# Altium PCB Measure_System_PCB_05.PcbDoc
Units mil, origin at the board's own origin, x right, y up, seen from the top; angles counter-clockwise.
Board outline 5905.51 x 3943.07 mil, 2 copper layers (Top Layer, Bottom Layer); 42 components, 30 nets, 113 pads, 0 vias.
Unrouted connection lines stored in the file: 1.
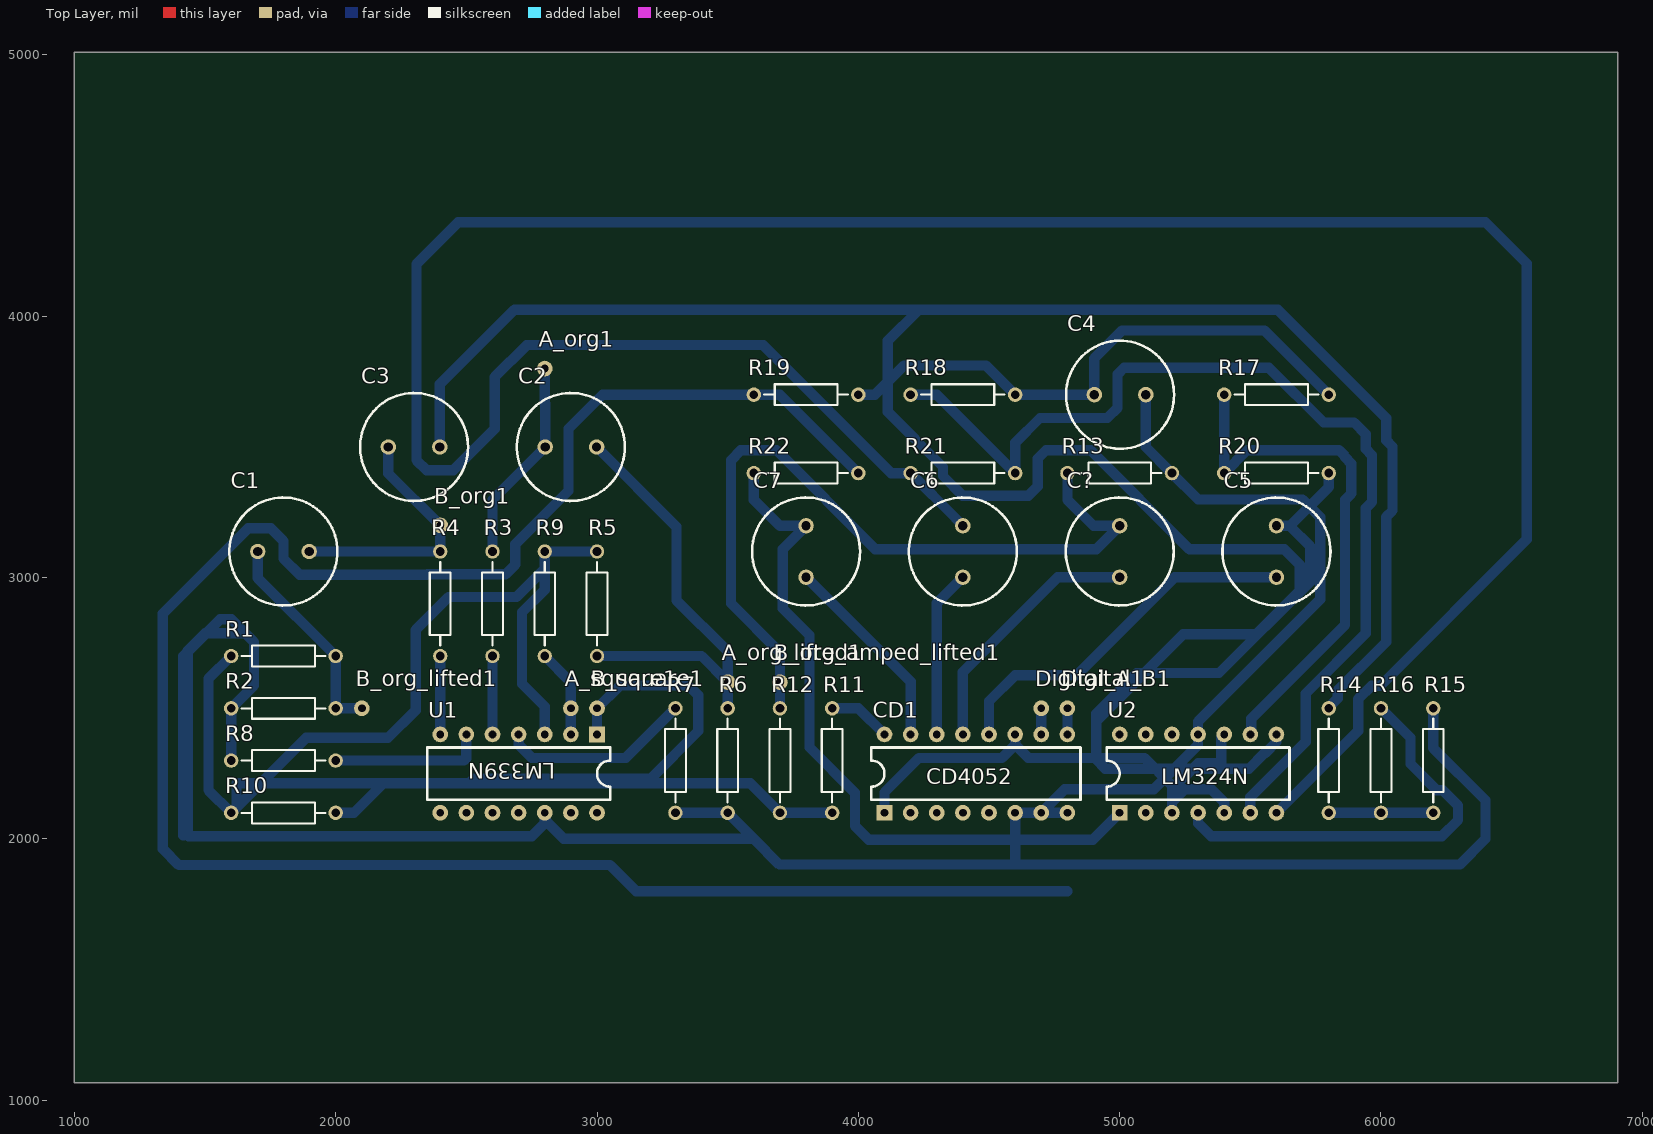
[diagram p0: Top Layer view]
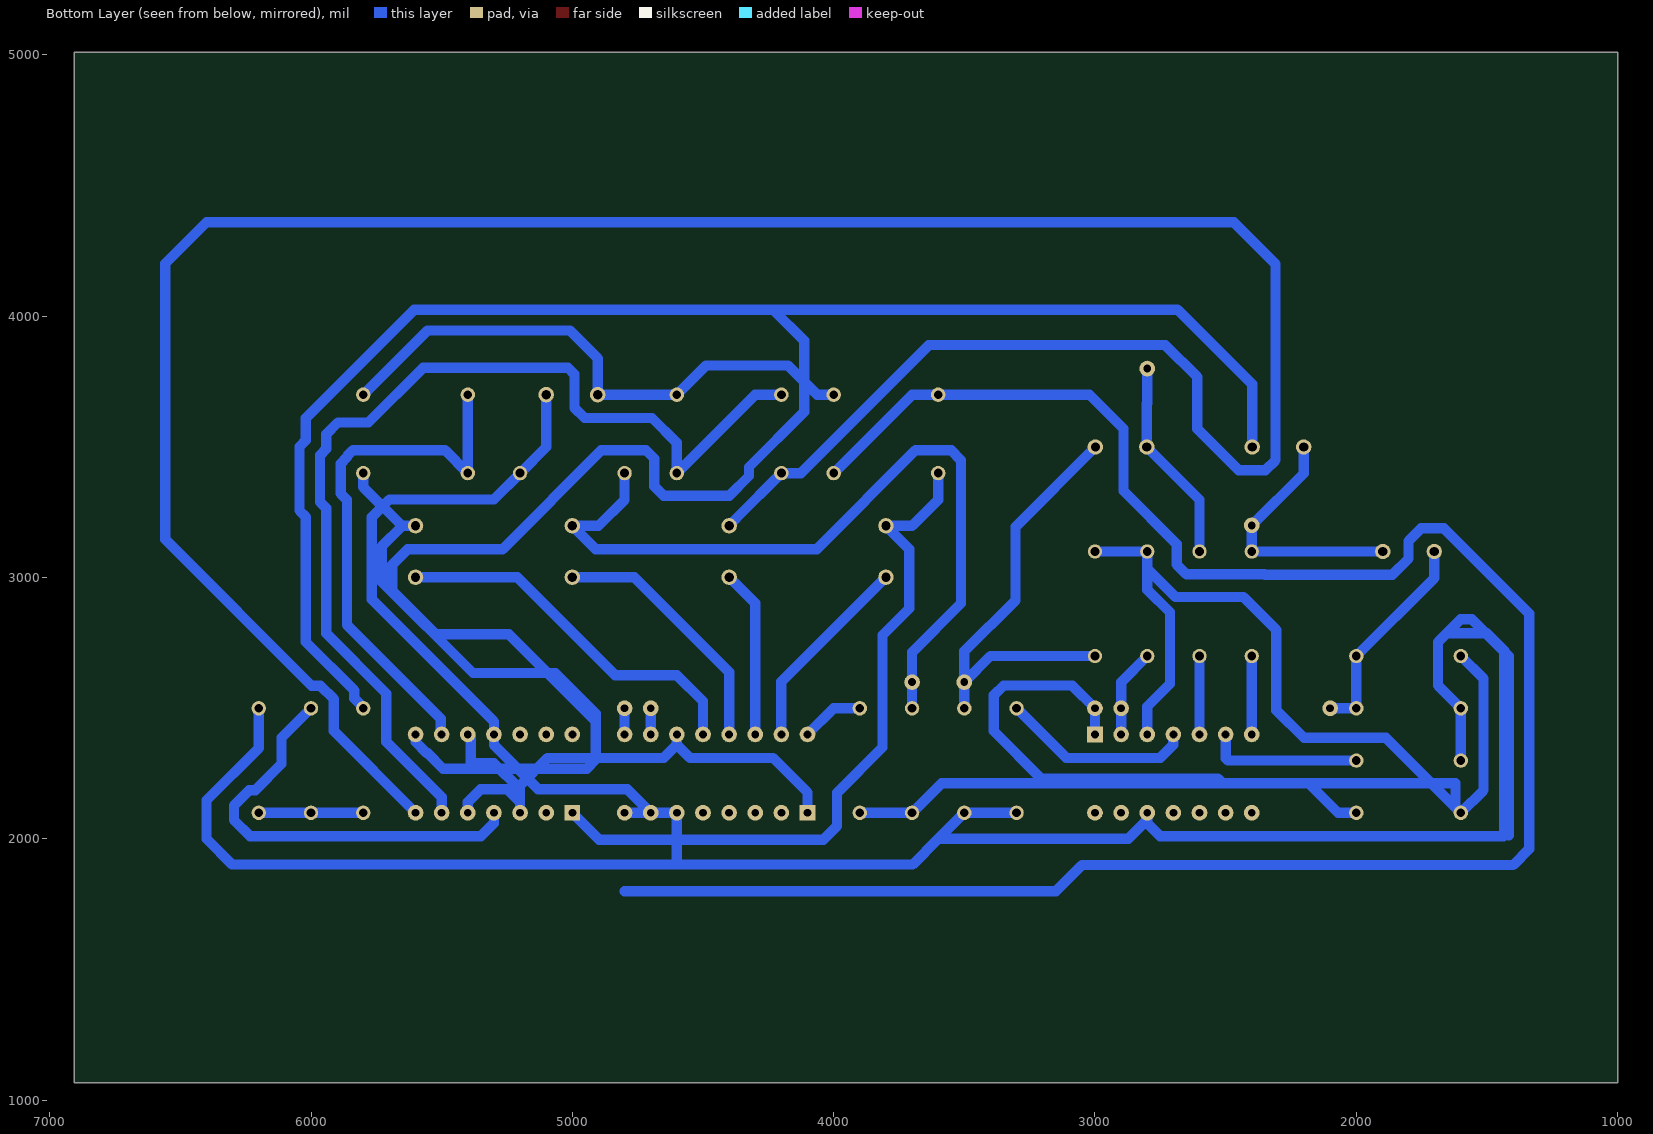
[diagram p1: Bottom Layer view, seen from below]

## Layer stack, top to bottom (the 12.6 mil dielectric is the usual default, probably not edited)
Top Solder: solder mask 0.4, Solder Resist, Dk 3.5
Top Layer: signal copper 1.4
Dielectric 1: dielectric 12.6, FR-4, Dk 4.8
Bottom Layer: signal copper 1.4
Bottom Solder: solder mask 0.4, Solder Resist, Dk 3.5

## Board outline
1000,1066.93 1000,5010 6905.51,5010 6905.51,1066.93

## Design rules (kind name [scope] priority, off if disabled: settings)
Clearance [All] p1: gap=39.37 ignorepadtopadclearanceinfootprint=FALSE
PolygonConnect [All] p1: connectstyle=Relief reliefconductorwidth=10 reliefentries=4 polygonreliefangle="90 Angle" airgapwidth=10
RoutingLayers [All] p1: top layer_v5=FALSE bottom layer_v5=TRUE
RoutingVias [All] p1: holewidth=28 width=50 viastyle="Through Hole" minholewidth=28 minwidth=50 maxholewidth=28 maxwidth=50
SolderMaskExpansion [All] p1: expansion=4 istentingtop=FALSE
Width [All] p1: maxlimit=393.7 minlimit=19.68 preferedwidth=39.37 minimp=50.000000 maximp=50.000000 favimp=50.000000
29 further rules are at their usual default settings.

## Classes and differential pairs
component class Part_Square: C1 C2 R1 R2 R3 R4 R5 R6 R7 R8 R9 R10 U1
component class Part_PGA: C3 C4 C5 C6 C7 C? CD1 R11 R12 R13 R14 R15 R16 R17 R18 R19 R20 R21 R22 U2
component class Measure_System_Main: A_org1 A_org_lifted1 A_square1 B_org1 B_org_amped_lifted1 B_org_lifted1 B_square1 Digital_A1 Digital_B1

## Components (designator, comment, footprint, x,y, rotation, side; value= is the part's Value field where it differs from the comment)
A_org1 "Hole" Hole 2800,3800 r90 top
A_org_lifted1 "Hole" Hole 3500,2600 r90 top
A_square1 "Hole" Hole 2900,2500 r90 top
B_org1 "Hole" Hole 2400,3200 r90 top
B_org_amped_lifted1 "Hole" Hole 3700,2600 r90 top
B_org_lifted1 "Hole" Hole 2100,2500 r0 top
B_square1 "Hole" Hole 3000,2500 r90 top
C1 "Cap Pol1" RB5-10.5 1800,3100 r180 top value=10u
C2 "Cap Pol1" RB5-10.5 2900,3500 r0 top value=10u
C3 "Cap Pol1" RB5-10.5 2300,3500 r0 top value=10u
C4 "Cap Pol1" RB5-10.5 5001.57,3700 r180 top value=10u
C5 "Cap Pol1" RB5-10.5 5600,3100 r270 top value=10u
C6 "Cap Pol1" RB5-10.5 4400,3100 r270 top value=10u
C7 "Cap Pol1" RB5-10.5 3800,3100 r270 top value=10u
C? "Cap Pol1" RB5-10.5 5000,3100 r90 top value=10u
CD1 "CD4052" CD4052 4100,2100 r90 top
Digital_A1 "Hole" Hole 4700,2500 r90 top
Digital_B1 "Hole" Hole 4800,2500 r90 top
R1 "Res2" AXIAL-0.4 1800,2700 r180 top value=100k
R2 "Res2" AXIAL-0.4 1800,2500 r0 top value=100k
R3 "Res2" AXIAL-0.4 2600,2900 r90 top value=1k
R4 "Res2" AXIAL-0.4 2400,2900 r90 top value=1k
R5 "Res2" AXIAL-0.4 3000,2900 r90 top value=100k
R6 "Res2" AXIAL-0.4 3500,2300 r90 top value=100k
R7 "Res2" AXIAL-0.4 3300,2300 r90 top value=10k
R8 "Res2" AXIAL-0.4 1800,2300 r180 top value=10k
R9 "Res2" AXIAL-0.4 2800,2900 r270 top value=10k
R10 "Res2" AXIAL-0.4 1800,2100 r180 top value=10k
R11 "Res2" AXIAL-0.4 3900,2300 r270 top value=200
R12 "Res2" AXIAL-0.4 3700,2300 r270 top value=100k
R13 "Res2" AXIAL-0.4 5000,3400 r180 top value=100k
R14 "Res2" AXIAL-0.4 5800,2300 r90 top value=100k
R15 "Res2" AXIAL-0.4 6200,2300 r270 top value=100k
R16 "Res2" AXIAL-0.4 6000,2300 r270 top value=100k
R17 "Res2" AXIAL-0.4 5600,3700 r180 top value=50k
R18 "Res2" AXIAL-0.4 4400,3700 r180 top value=24k
R19 "Res2" AXIAL-0.4 3800,3700 r180 top value=12k
R20 "Res2" AXIAL-0.4 5600,3400 r0 top value=100k
R21 "Res2" AXIAL-0.4 4400,3400 r180 top value=100k
R22 "Res2" AXIAL-0.4 3800,3400 r180 top value=100k
U1 "LM339N" LM339N 3000,2400 r270 top
U2 "LM324N" LM324N 5000,2100 r90 top

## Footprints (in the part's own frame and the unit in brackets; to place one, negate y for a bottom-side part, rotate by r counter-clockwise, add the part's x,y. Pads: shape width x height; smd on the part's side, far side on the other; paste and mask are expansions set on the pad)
AXIAL-0.4 [mm] "Axial Device, Thru-Hole; 2 Leads; 0.4 in Pin Spacing"
  round 1.4 hole 0.85: 1(-5.08,0) 2(5.08,0)
  silkscreen extent -4.06,-1.02 4.06,1.02
CD4052 [mil]
  rect 60x60 hole 30: 1(0,0)
  round 60 hole 30 mask+4: 2(0,-100) 3(0,-200) 4(0,-300) 5(0,-400) 6(0,-500) 7(0,-600) 8(0,-700) 9(300,-700) 10(300,-600) 11(300,-500) 12(300,-400) 13(300,-300) 14(300,-200) 15(300,-100) 16(300,0)
  silkscreen extent 50,-750 250,50
Hole [mil]
  round 60 hole 30 mask+4: 1(0,0)
LM324N [mil]
  rect 60x60 hole 30: 1(0,0)
  round 60 hole 30 mask+4: 2(0,-100) 3(0,-200) 4(0,-300) 5(0,-400) 6(0,-500) 7(0,-600) 8(300,-600) 9(300,-500) 10(300,-400) 11(300,-300) 12(300,-200) 13(300,-100) 14(300,0)
  silkscreen extent 50,-650 250,50
LM339N [mil]
  rect 60x60 hole 30: 1(0,0)
  round 60 hole 30 mask+4: 2(0,-100) 3(0,-200) 4(0,-300) 5(0,-400) 6(0,-500) 7(0,-600) 8(300,-600) 9(300,-500) 10(300,-400) 11(300,-300) 12(300,-200) 13(300,-100) 14(300,0)
  silkscreen extent 50,-650 250,50
RB5-10.5 [mm] "Capacitor (Radial); 2 Leads"
  round 1.5 hole 0.9: 1(-2.5,0) 2(2.5,0)
  silkscreen extent -5.25,-5.25 5.25,5.25

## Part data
C1 C2 C3 C4 C5 C6 C7 C?: "Polarized Capacitor (Radial)"
R1 R2 R3 R4 R5 R6 R7 R8 R9 R10 R11 R12 R13 R14 R15 R16 R17 R18 R19 R20 R21 R22: "Resistor"

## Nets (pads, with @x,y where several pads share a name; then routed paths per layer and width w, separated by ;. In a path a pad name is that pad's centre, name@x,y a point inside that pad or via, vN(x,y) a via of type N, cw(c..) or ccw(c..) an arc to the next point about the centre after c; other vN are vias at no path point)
+5: R1.2 R5.2 R9.1 R10.2 R11.2 R12.2 U1.3 | length 5830.9
  Bottom Layer w39.37: R1.2 1513,2613 1513,2187 R10.2 1620,2120 ; U1.3 2800,2507 2713,2594 2713,2867 2800,2954 2800,3034.64 ; R5.2 R9.1 2800,3034.64 ; R11.2 R12.2 3587,2213 1713,2213 ; 1620,2120 1713,2213 ; 1620,2120 1620,2213 1713,2213 ; 1713,2213 1887,2387 2200,2387 2306,2493 2306,2800 2431.5,2925.5 2690.86,2925.5 2800,3034.64
+12: R16.1 U2.4 | length 1644.4
  Bottom Layer w39.37: U2.4 5300,2060 5350,2010 6232.49,2010 6294.94,2072.45 6294.94,2127.55 6235.88,2186.61 6213.39,2186.61 6113,2287 6113,2387 R16.1
B_org: B_org1.1 C1.1 C3.1 R4.2 | length 983.8
  Bottom Layer w39.37: C1.1 R4.2 B_org1.1 2201.57,3398.43 C3.1
B_org_amp_1: C3.2 CD1.1 CD1.11 R14.2 U2.3 U2.5 U2.10 | length 11174.7
  Bottom Layer w39.37: C3.2 2398.43,3739.48 2683.94,4025 4232,4025 ; CD1.1 4100,2178 4232,2310 4550,2310 4600,2360 ; CD1.11 4600,2360 ; U2.3 5200,2140 ; U2.5 5400,2140 5350,2190 5250,2190 5200,2140 ; U2.10 5389,2389 5389,2290 5300,2290 5200,2190 ; R14.2 5800,2504.26 5834.65,2538.91 5834.65,2568.49 6020,2753.85 6020,3232.43 6044.09,3256.52 6044.09,3501.11 6020,3525.2 6020,3610 5605,4025 4232,4025 ; 4232,4025 4113,3906 4113,3634.4 4324,3423.4 4324,3389 4400,3313 4650,3313 4687,3350 4687,3456 4718,3487 4889,3487 5267,3109 5630,3109 5689,3050 5689,2950 5522.7,2783.7 5243.7,2783.7 4910,2450 4910,2317 4903,2310 ; 4600,2360 4650,2310 4903,2310 ; 4903,2310 5095,2310 5200,2205 5200,2190 ; 5200,2140 5200,2190
B_org_amp_2.5: C5.2 CD1.12 | length 1423.6
  Bottom Layer w39.37: CD1.12 4500,2527 4600,2627 4836.33,2627 5210.9,3001.57 C5.2
B_org_amp_5: C6.2 CD1.14 | length 643
  Bottom Layer w39.37: CD1.14 4300,2901.57 C6.2
B_org_amp_10: C7.2 CD1.15 | length 767.3
  Bottom Layer w39.37: C7.2 4200,2601.57 CD1.15
B_org_amped: C?.1 CD1.13 | length 989
  Bottom Layer w39.37: CD1.13 4400,2638.64 4762.93,3001.57 C?.1
Digital_A: CD1.10 Digital_A1.1 | length 100
  Bottom Layer w39.37: CD1.10 Digital_A1.1
Digital_B: CD1.9 Digital_B1.1 | length 100
  Bottom Layer w39.37: CD1.9 Digital_B1.1
GND: C4.1 CD1.6 CD1.7 CD1.8 R2.1 R6.1 R7.1 R8.2 R13.1 R15.1 U1.12 U2.11 | length 11731.4
  Bottom Layer w39.37: 1417,2013 1417,2700 1434,2717 ; R8.2 R2.1 1687,2587 1687,2754 1600,2841 1558,2841 1504,2787 ; 1650,2787 1504,2787 ; R7.1 R6.1 3599,2001 ; CD1.8 CD1.7 ; C4.1 5100,3500 R13.1 5301,3299 5700,3299 5768,3231 5768,2917.64 5300,2449.64 U2.11 5300,2360 5130,2190 4790,2190 CD1.7 ; R15.1 6200,2347.87 6400,2147.87 6400,2000 6302,1902 4600,1902 ; 1434,2717 1434,2721 1500,2787 1504,2787 ; 1434,2717 1434,2013 1437,2010 2750,2010 2800,2060 U1.12 2803.95,2096.05 2803.95,2070.11 2873.06,2001 3599,2001 ; 1434,2717 1504,2787 ; 3599,2001 3698,1902 4600,1902 ; 4600,1902 CD1.6 CD1.7
NetA_org1_1: A_org1.1 C2.1 R3.2 | length 784.1
  Bottom Layer w39.37: R3.2 2600,3298.43 C2.1 2801.57,3665.75 2800,3667.33 A_org1.1
NetA_org_lifted1_1: A_org_lifted1.1 C2.2 R5.1 R6.2 | length 1749.2
  Bottom Layer w39.37: C2.2 3303.97,3194.45 3303.97,2913.83 3500,2717.8 A_org_lifted1.1 ; R5.1 3400,2700 A_org_lifted1.1 ; R6.2 3500,2549 A_org_lifted1.1
NetA_square1_1: A_square1.1 R9.2 U1.2 | length 341.4
  Bottom Layer w39.37: R9.2 2900,2600 A_square1.1 U1.2
NetB_org_amped_lifted1_1: B_org_amped_lifted1.1 C?.2 R12.1 R13.2 | length 3066.4
  Bottom Layer w39.37: R12.1 B_org_amped_lifted1.1 3700,2714 3513,2901 3513,3450 3550,3487 3687,3487 4065,3109 4910.57,3109 C?.2 4900,3198.43 4800,3298.43 R13.2
NetB_org_lifted1_1: B_org_lifted1.1 C1.2 R1.1 R2.2 | length 823.6
  Bottom Layer w39.37: C1.2 1701.58,2998.42 R1.1 R2.2 2049,2500 B_org_lifted1.1
NetB_square1_1: B_square1.1 R10.1 U1.1 | length 2192
  Bottom Layer w39.37: R10.1 2070,2100 2183,2213 2511,2213 2529,2231 3205,2231 3387,2413 3387,2550 3350,2587 3087,2587 B_square1.1 U1.1
NetC4_2: C4.2 R17.1 R18.1 R19.1 | length 2178
  Bottom Layer w39.37: R19.1 4063,3700 4175,3812 4488,3812 R18.1 C4.2 4903.15,3838.94 5010.28,3946.07 5553.93,3946.07 R17.1
NetC5_1: C5.1 R20.2 U2.8 | length 2540.7
  Bottom Layer w39.37: U2.8 5600,2371.36 5556.37,2327.72 5553.67,2327.72 5494.94,2269 4945,2269 4910,2304 4910,2480 5065,2635 5380,2635 5729,2984 5729,3119.43 5650.97,3197.46 ; C5.1 5650,3198.43 5650.97,3197.46 ; R20.2 5800,3346.5 5650.97,3197.46
NetC6_1: C6.1 R21.2 U2.7 | length 10358.3
  Bottom Layer w39.37: C6.1 4373.75,3224.68 4373.75,3226.25 R21.2 4126,3400 3636,3890 2731,3890 2609,3768 2609,3570 2450,3411 2348,3411 2309,3450 2309,4200 2469,4360 6400,4360 6558,4202 6558,3146.64 5997.97,2586.61 5964.12,2586.61 5913.39,2535.88 5913.39,2413.39 U2.7
NetC7_1: C7.1 R22.2 U2.1 | length 2720.2
  Bottom Layer w39.37: R22.2 3600,3298.43 3700,3198.43 C7.1 3711,3109.43 3711,2882 3813,2780 3813,2351 3987,2177 3987,2050 4040,1997 4897,1997 U2.1
NetCD1_16: CD1.16 R11.1 | length 241.4
  Bottom Layer w39.37: R11.1 4000,2500 CD1.16
NetR3_1: R3.1 U1.5 | length 300
  Bottom Layer w39.37: U1.5 2600,2549 R3.1
NetR4_1: R4.1 U1.7 | length 300
  Bottom Layer w39.37: U1.7 R4.1
NetR7_2: R7.2 U1.4 | length 739.4
  Bottom Layer w39.37: U1.4 2700,2360 2750,2310 3110,2310 R7.2
NetR8_1: R8.1 U1.6 | length 594.7
  Bottom Layer w39.37: R8.1 2491,2300 2500,2309 U1.6
NetR14_1: R14.1 R15.2 R16.2 | length 400
  Bottom Layer w39.37: R14.1 R16.2 R15.2
NetR17_2: R17.2 R20.1 U2.9 | length 2042.2
  Bottom Layer w39.37: R17.2 R20.1 5487,3487 5839.46,3487 5862.52,3463.94 5862.52,3459.97 5886.61,3435.88 5886.61,3321.75 5862.52,3297.66 5862.52,2819.08 5503.95,2460.5 5503.95,2403.95 U2.9
NetR18_2: R18.2 R21.1 U2.6 | length 3933.4
  Bottom Layer w39.37: R18.2 4300,3700 R21.1 4600,3515.74 4695.26,3611 4953,3611 4992,3650 4992,3779 5016.49,3803.49 5570.51,3803.49 5780.35,3593.65 5896.94,3593.65 5941.26,3549.33 5941.26,3492.59 5965.35,3468.49 5965.35,3289.14 5941.26,3265.05 5941.26,2786.46 5711.56,2556.76 5711.56,2371.56 5500,2160 U2.6
NetR19_2: R19.2 R22.1 U2.2 | length 7933.5
  Bottom Layer w39.37: R22.1 3700,3700 R19.2 3021,3700 2891,3570 2891,3332 2686.62,3127.62 2686.62,3050 2650,3013.38 2351,3013.38 2348.62,3011 1862.15,3011 1800,3073.15 1800,3140.36 1751.78,3188.58 1664.88,3188.58 1338.26,2861.96 1338.26,1961.74 1400,1900 3050,1900 3150,1800 4800,1800
pads on no net: CD1.2 CD1.3 CD1.4 CD1.5 U1.8 U1.9 U1.10 U1.11 U1.13 U1.14 U2.12 U2.13 U2.14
